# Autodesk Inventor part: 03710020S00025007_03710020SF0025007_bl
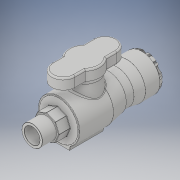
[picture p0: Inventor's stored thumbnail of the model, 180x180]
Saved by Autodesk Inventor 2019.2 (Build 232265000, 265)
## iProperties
Created: 2022-04
Part Number: 03710020S00025007_03710020SF0025007_bl
Material: Generic
Description: PA Ball Valve Series 1 25mm x Male 3/4''
Document SubType Name: Modeling
Designer: Lenora
Density: 1 g/cm^3
Appearance: Default
Author: Lenora
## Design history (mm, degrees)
derived "0371002.ipt"
feature "Solid1::0371002.ipt" dims "ScaleForDerivedMember" = 10
tag "TaggingFeature1"
body "Solid1"
other parameters: "d0" = 148 [user parameter], "d16" = 81.4 [user parameter], "d19" = 1 [user parameter], "d20" = 37 [user parameter], "d22" = 85 deg [user parameter], "d25" = 1 [user parameter], "d34" = 26.64 [user parameter], "d35" = 14.8 [user parameter], "d37" = 0 [user parameter], "d39" = 360 deg [user parameter], "d43" = 27 [user parameter], "d45" = 70 deg [user parameter], "d46" = 70 deg [user parameter], "d48" = 0 [user parameter], "d57" = 2 [user parameter], "d63" = 53 [user parameter], "d71" = 7.4 [user parameter], "d72" = 11.1 [user parameter], "d73" = 26.64 [user parameter], "d76" = 54 [user parameter], "d77" = 16.2 [user parameter], "d78" = 39.96 [user parameter], "d79" = 18.5 [user parameter], "d80" = 100 deg [user parameter], "d81" = 12.58 [user parameter], "d83" = 22.95 [user parameter], "d84" = 11.1 [user parameter], "d85" = 26.5 [user parameter], "d90" = 0 [user parameter], "d91" = 7.95 [user parameter], "d92" = 45 deg [user parameter], "d93" = 4.24 [user parameter], "d94" = 1.696 [user parameter], "d95" = 2.12 [user parameter], "d96" = 2.12 [user parameter], "d97" = 2.12 [user parameter], "d98" = 2.12 [user parameter], "d111" = 0.5 [user parameter], "d112" = 2 [user parameter], "d114" = 7.42 [user parameter], "d115" = 0 [user parameter], "d117" = 360 deg [user parameter], "d119" = 42.93 [user parameter], "d120" = 47 [user parameter], "d121" = 25 [user parameter], "d122" = 1 [user parameter], "d123" = 89 deg [user parameter], "d124" = 80 deg [user parameter], "d126" = 18 [user parameter], "d127" = 14.4 [user parameter], "d129" = 26.441 [user parameter], "d130" = 17 [user parameter], "d132" = 49.29 [user parameter], "d134" = 0 [user parameter], "d135" = 0.25 [user parameter], "d" = 25 [user parameter], "A1" = 27 [user parameter], "A2" = 54 [user parameter], "H_" = 148 [user parameter], "E_" = 53 [user parameter], "E1" = 47 [user parameter], "l2" = 18 [user parameter], "R" = 26.441 [user parameter]
